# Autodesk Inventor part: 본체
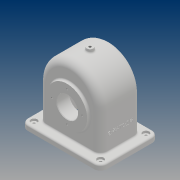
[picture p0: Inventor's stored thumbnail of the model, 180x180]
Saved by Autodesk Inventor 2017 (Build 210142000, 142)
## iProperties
Part Number: 본체
Material: 일반
Document SubType Name: Modeling
Designer: 20
Density: 1 g/cm^3
Appearance: 기본값
Mass: 404.407 g
Surface Area: 1182.65 cm^2
Volume: 404.407 cm^3
Author: 20
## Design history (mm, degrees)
sketch "스케치1"
  geometry: L1 (58, 0)-(58, -78); L2 (-58, 0)-(-58, -78); L3 (58, -78)-(-58, -78); A1 r 58 centre (0, 0) between (58, 0) and (-58, 0); 1 further point
  constraints: 6 end point, 2 point on circle, 2 tangent, 2 vertical, 1 centre point, 1 coincident, 1 horizontal
  dimensions: "d0" = 116 diameter of A1; "d1" = 78 distance from line of L3 point (0, 0)
extrude "돌출1" new body sketch "스케치1" stored distance "d2" = 77; taper "d3" = 0 deg
fillet "모깎기2" dims "d6" = 13
sketch "스케치4"
  geometry: L1 (-45, -78)-(45, -78) reference; C1 r 38 at (0, -13); 1 further point
  constraints: 1 centre point, 1 vertical alignment
  dimensions: "d11" = 76 diameter of C1; "d22" = 65 distance from line of L1 C1.centre
extrude "돌출3" join sketch "스케치4" distance "d13" = 5; taper "d14" = 0 deg
sketch "스케치6"
  geometry: L1 (120, 16.5)-(-30, 16.5); L2 (-30, 16.5)-(-30, -93.5); L3 (-30, -93.5)-(120, -93.5); L4 (120, -93.5)-(120, 16.5); L5 (120, 16.5)-(-30, -93.5); L6 (-30, 16.5)-(120, -93.5); L7 (90, -77)-(0, -77) reference; L8 (-13, -13)-(-13, -64) reference; L9 (0, 0)-(90, 0) reference; L10 (103, -13)-(103, -64) reference; A1 r 13 centre (90, -64) between (90, -77) and (103, -64) reference; A2 r 13 centre (0, -64) between (-13, -64) and (0, -77) reference; A3 r 13 centre (0, -13) between (0, 0) and (-13, -13) reference; A4 r 13 centre (90, -13) between (103, -13) and (90, 0) reference; 1 further point
  constraints: 12 end point, 2 midpoint, 2 parallel, 1 horizontal, 1 perpendicular
  dimensions: "d18" = 150 distance of L3.end L2.end; "d19" = 110 distance of L2.end L1.end
extrude "돌출5" join sketch "스케치6" distance "d20" = 10; taper "d21" = 0 deg
node "작업 평면1"
sketch "스케치9"
  geometry: C1 r 6 at (0, 0); 1 further point
  constraints: 1 centre point, 1 coincident
  dimensions: "d27" = 12 diameter of C1
extrude "돌출7" join sketch "스케치9" stored distance "d28" = 15; taper "d29" = 5 deg
sketch "스케치10"
  geometry: C1 r 38 at (0, 0) reference; C2 r 20 at (0, 0); 1 further point
  constraints: 1 centre point, 1 coincident
  dimensions: "d30" = 40 diameter of C2
extrude "돌출8" cut sketch "스케치10" stored distance "d31" = 15; taper "d32" = 0 deg
fillet "모깎기3" dims "d34" = 12
sketch "스케치13"
  geometry: C1 r 6 at (-108, 4.5); C2 r 6 at (18, 4.5); C3 r 6 at (18, -81.5); C4 r 6 at (-108, -81.5); A1 r 12 centre (-108, 4.5) between (-108, 16.5) and (-120, 4.5) reference; A2 r 12 centre (18, 4.5) between (30, 4.5) and (18, 16.5) reference; A3 r 12 centre (18, -81.5) between (18, -93.5) and (30, -81.5) reference; A4 r 12 centre (-108, -81.5) between (-120, -81.5) and (-108, -93.5) reference; 1 further point
  constraints: 4 centre point, 4 coincident
  dimensions: "d35" = 12 diameter of C1; "d36" = 12 diameter of C2; "d37" = 12 diameter of C3; "d38" = 12 diameter of C4
extrude "돌출9" cut sketch "스케치13" distance "d39" = 4; taper "d40" = 0 deg
sketch "스케치14"
  geometry: C1 r 6 at (0, 0) reference; C2 r 2.5 at (0, 0); C3 r 6 at (0, -86) reference; C4 r 2.5 at (0, -86); C5 r 6 at (-126, -86) reference; C6 r 2.5 at (-126, -86); C7 r 6 at (-126, 0) reference; C8 r 2.5 at (-126, 0); 1 further point
  constraints: 4 centre point, 4 coincident
  dimensions: "d41" = 5 diameter of C2; "d42" = 5 diameter of C4; "d43" = 5 diameter of C6; "d44" = 5 diameter of C8
extrude "돌출10" cut sketch "스케치14" distance "d45" = 20; taper "d46" = 0 deg
hole "구멍1" diameter "d49" = 4.459; stored, may be unused: countersink angle "d53" = 90 deg, drill point angle "d55" = 118 deg; dims "d47" = 10, "d48" = 10, "d50" = 10, "d51" = 4, "d52" = 2, "d54" = 15
sketch "스케치16"
  geometry: C1 r 20 at (0, 13) reference; C2 r 38 at (0, 13); 1 further point
  constraints: 1 centre point, 1 coincident
  dimensions: "d67" = 76 diameter of C2
extrude "돌출11" join sketch "스케치16" distance "d68" = 10; taper "d69" = 0 deg
sketch "스케치17"
  geometry: L1 (0, 51)-(0, 0) reference; L2 (78, 68.5)-(78, -17.5) reference; L3 (0, -13)-(68, -13) reference; 3 further points
  constraints: 1 midpoint, 1 other
  dimensions: "d70" = 40 distance from line of L2 point (38, 25.5); "d124" = 38.5 distance from line of L3 point (38, 25.5)
feature "엠보싱1" sketch "스케치17" dims "d0" = 116, "d1" = 78, "d71" = 0.5, "d72" = 0
fillet "모깎기4" dims "d73" = 3
fillet "모깎기5" dims "d74" = 3
fillet "모깎기6" dims "d75" = 3
chamfer "모따기1" distance "d76" = 1; stored, may be unused: second distance "d77" = 2, angle "d78" = 45 deg
fillet "모깎기7" dims "d79" = 3
sketch "스케치20"
  geometry: L1 (58, -65)-(58, 0) reference; L2 (-58, 0)-(-58, -65) reference; L3 (63, -78)-(-63, -78) reference; L4 (75, -78)-(63, -78) reference; L5 (-63, -78)-(-75, -78) reference; L6 (-52, -78)-(-52, 0); L7 (52, 0)-(52, -78); A1 r 58 centre (0, 0) between (58, 0) and (-58, 0) reference; A2 r 52 centre (0, 0) between (52, 0) and (-52, 0); 1 further point
  constraints: 4 end point, 2 point on circle, 2 point on line, 1 centre point, 2 other
  dimensions: "d91" = 6 radial gap between concentric circles of A1 A2
extrude "돌출12" cut sketch "스케치20" stored distance "d92" = 67; taper "d93" = 0 deg
fillet "모깎기8" dims "d94" = 8
sketch "스케치21"
  geometry: C1 r 20 at (0, 0) reference; C2 r 28 at (0, 0); 1 further point
  constraints: 1 centre point, 1 coincident
  dimensions: "d95" = 56 diameter of C2
extrude "돌출13" join sketch "스케치21" distance "d96" = 24; taper "d97" = 0 deg
feature "면 기울기2" dims angle "d98" = 40 deg
sketch "스케치22"
  geometry: C1 r 20 at (0, 0) reference; 2 further points
  constraints: 1 vertical alignment
  dimensions: "d99" = 29 distance of C1.centre point (0, 29)
hole "구멍4" sketch "스케치22" at (0, 29) diameter "d100" = 3.242; stored, may be unused: countersink angle "d104" = 90 deg, drill point angle "d106" = 118 deg; dims "d101" = 8, "d102" = 4, "d103" = 2, "d105" = 10
sketch "스케치23"
  geometry: C1 r 21 at (0, 0) reference; 2 further points
  constraints: 1 vertical alignment
  dimensions: "d110" = 29 distance of C1.centre point (0, -29)
hole "구멍5" sketch "스케치23" at (0, -29) diameter "d111" = 3.242; stored, may be unused: countersink angle "d115" = 90 deg, drill point angle "d117" = 118 deg; dims "d112" = 8, "d113" = 4, "d114" = 2, "d116" = 10
chamfer "모따기2" distance "d121" = 1; stored, may be unused: second distance "d122" = 2, angle "d123" = 45 deg
node "솔리드1"
pattern_circular "원형 패턴3" dims angle "d108" = 360 deg
pattern_circular "원형 패턴4" dims angle "d119" = 360 deg
other parameters: "d26" = 64
